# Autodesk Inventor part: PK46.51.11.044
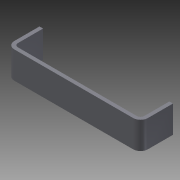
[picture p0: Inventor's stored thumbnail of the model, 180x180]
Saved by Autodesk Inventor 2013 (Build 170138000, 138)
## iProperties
Shininess: 64.0
Length Units: 11269
Angle Units: 11279
Time Units: 11290
Mass Units: 11283
Length Display Precision: 3
Angle Display Precision: 2
Compacted: True
Part Number: PK46.51.11.044
Document SubType Name: Листовой материал
Created: 2005-02
Material: Steel, Mild
Designer: =<Author>
Manufacturer: Standard
Standards Organization: Custom
Description: bracket
Density: 7.86 g/cm^3
Sheet Metal Rule: По умолчанию
Mass: 24.3876 g
Surface Area: 35.7644 cm^2
Volume: 3.10275 cm^3
Density: 0.0
Volumn: 0.0
Area: 0.0
PropertySet Name: Model Information
Control State: 0
Master: False
Checked Out: False
Checked Out Date: 2008-10-15
Last Check In Date: 2008-10-15
Толщина: 2.000 mm
Радиус_гибки: 2.000 mm
Ширина_просечки: 2.000 mm
Глубина_просечки: 1.000 mm
Размер_высечки: 8.000 mm
Минимальный_остаток: 4.000 mm
Радиус_перехода: 2.000 mm
JacobiRadiusSize: 2.000 mm
GapSize: 2.000 mm
d0: 74.000 mm
d1: 18.000 mm
d2: 18.000 mm
d3: 15.000 mm
d4: 2.000 mm
d5: 1.000 mm
d6: 4.000 mm
d7: 2.000 mm
d8: 2.000 mm
d9: 2.000 mm
Author: PVitaliy
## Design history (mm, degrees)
node "ФлнОтгиб1"
body "Solid1"
sketch "Эскиз1"
  geometry: L1 (0, 0)-(74, 0); L2 (74, 0)-(74, 18); L3 (0, 0)-(0, 18)
  constraints: 6 end point, 1 horizontal, 1 parallel, 1 perpendicular, 1 other
  dimensions: "d0" = 74 distance of L1.start L1.end; "d1" = 18 distance of L1.start L3.end; "d2" = 18 distance of L1.end L2.end (= d1)
feature "Пластина1" dims "d3" = 15, "d4" = 2 (= Ширина_просечки), "d6" = 4 (= Минимальный_остаток), "d8" = 2 (= Радиус_гибки), "d9" = 2, "Толщина" = 2
feature "Изгиб1" dims "d4" = 2 (= Ширина_просечки), "d5" = 1 (= Глубина_просечки), "d6" = 4 (= Минимальный_остаток), "d7" = 2 (= Радиус_гибки), "d8" = 2 (= Радиус_гибки), "d9" = 2, "Толщина" = 2, "Зазор_стыка" = 0.01
other parameters: "Радиус_гибки" = 2 (= Толщина), "Ширина_просечки" = 2 (= Толщина), "Глубина_просечки" = 1 (= 0.5 x Толщина), "Размер_высечки" = 8 (= 4 x Толщина), "Минимальный_остаток" = 4 (= 2 x Толщина), "Радиус_перехода" = 2 (= Радиус_гибки), "JacobiRadiusSize" = 2 (= Толщина), "GapSize" = 2 (= Толщина)
